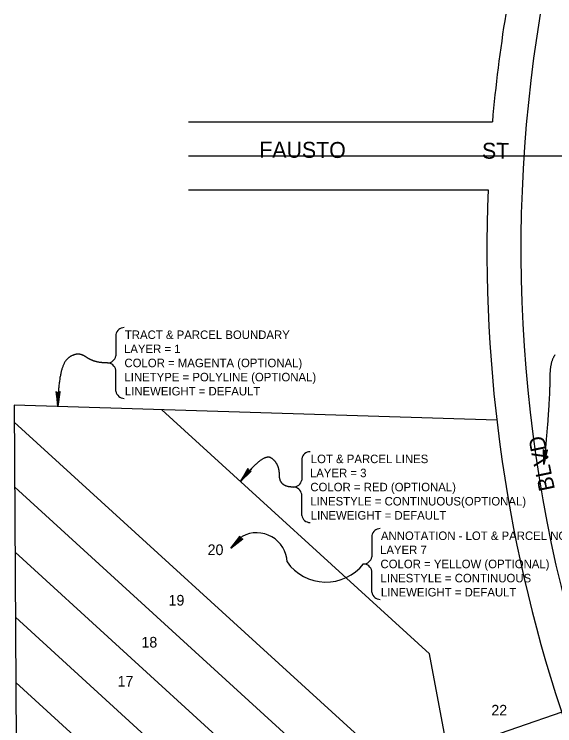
# Model space of a CAD drawing. Extents: x 6387474 to 6390971, y 1972046 to 1973920.
# Drawn here: x 6389073 to 6389581, y 1973251 to 1973920 of the extents above; entities that cross this region are included whole.
import ezdxf

# ---------------------------------------------------------------- set-up
doc = ezdxf.new("R2010")
doc.units = 0
for name, color, linetype in [('1', 7, 'Continuous'), ('2', 7, 'Continuous'), ('3', 7, 'Continuous'), ('4', 7, 'Continuous'), ('7', 7, 'Continuous'), ('8', 7, 'Continuous')]:
    doc.layers.add(name, color=color, linetype=linetype)

msp = doc.modelspace()

# ---------------------------------------------------------------- linework, layer by layer
at = {"layer": '1'}
for p, q in [((6389526.67, 1973538.46), (6389072.58, 1973552.73)), ((6389072.58, 1973552.73), (6389079.62, 1972388))]:
    msp.add_line(p, q, dxfattribs=at)
at = {"layer": '2'}
msp.add_line((6389236.57, 1973787.32), (6389892.25, 1973787.32), dxfattribs=at)
msp.add_arc((6390899.27, 1973699.34), 1350, 170.57423, 198.92361, dxfattribs=at)
at = {"layer": '3'}
for p, q in [((6389463.19, 1973318.92), (6389211.42, 1973548.37)), ((6389461.63, 1973182.31), (6389072.67, 1973536.78)), ((6389431.59, 1973148.83), (6389073.04, 1973475.59)), ((6389401.27, 1973115.57), (6389073.41, 1973414.37)), ((6389370.96, 1973082.31), (6389073.78, 1973353.15)), ((6389479.97, 1973230.27), (6389463.19, 1973318.92)), ((6389340.65, 1973049.05), (6389074.15, 1973291.92)), ((6389587.7, 1973263.79), (6389480.83, 1973227.16))]:
    msp.add_line(p, q, dxfattribs=at)
at = {"layer": '4'}
for p, q in [((6389236.57, 1973819.32), (6389522.49, 1973819.32)), ((6389236.57, 1973755.32), (6389518.4, 1973755.32))]:
    msp.add_line(p, q, dxfattribs=at)
for start, end in [(170.7944, 175.01954), (177.67854, 198.92361)]:
    msp.add_arc((6390899.27, 1973699.34), 1382, start, end, dxfattribs=at)
at = {"layer": '8'}
for p, q in [((6389168.16, 1973619.05), (6389168.16, 1973599.07)), ((6389168.16, 1973565.76), (6389168.16, 1973585.74)), ((6389111.81, 1973565.47), (6389113.61, 1973551.44)), ((6389113.61, 1973551.44), (6389115.81, 1973565.41)), ((6389570.35, 1973511.03), (6389571.01, 1973496.9)), ((6389571.01, 1973496.9), (6389574.33, 1973510.65)), ((6389343.08, 1973502.29), (6389343.08, 1973482.31)), ((6389292.5, 1973493.16), (6389285.46, 1973480.89)), ((6389285.46, 1973480.89), (6389295.65, 1973490.7)), ((6389343.08, 1973449), (6389343.08, 1973468.98)), ((6389284.72, 1973429.64), (6389276.36, 1973418.23)), ((6389276.36, 1973418.23), (6389287.2, 1973429.31)), ((6389276.36, 1973418.23), (6389287.58, 1973426.84)), ((6389409.08, 1973429.97), (6389409.08, 1973409.99)), ((6389409.08, 1973376.69), (6389409.08, 1973396.67))]:
    msp.add_line(p, q, dxfattribs=at)
for points in [[(6389124.97, 1973598.13), (6389124.64, 1973597.91), (6389124.31, 1973597.68), (6389123.98, 1973597.44), (6389123.65, 1973597.19), (6389123.32, 1973596.93), (6389122.98, 1973596.66), (6389122.65, 1973596.38), (6389122.33, 1973596.07), (6389122.01, 1973595.74), (6389121.7, 1973595.39), (6389121.39, 1973595.02), (6389121.09, 1973594.63), (6389120.8, 1973594.22), (6389120.51, 1973593.78), (6389120.22, 1973593.32), (6389119.95, 1973592.84), (6389119.68, 1973592.34), (6389119.41, 1973591.81), (6389119.15, 1973591.26), (6389118.9, 1973590.7), (6389118.65, 1973590.11), (6389118.41, 1973589.49), (6389118.17, 1973588.86), (6389117.94, 1973588.2), (6389117.72, 1973587.53), (6389117.5, 1973586.83), (6389117.29, 1973586.1), (6389117.08, 1973585.36), (6389116.88, 1973584.59), (6389116.69, 1973583.81), (6389116.5, 1973583), (6389116.32, 1973582.17), (6389116.14, 1973581.31), (6389115.97, 1973580.44), (6389115.8, 1973579.54), (6389115.64, 1973578.62), (6389115.49, 1973577.68), (6389115.34, 1973576.72), (6389115.2, 1973575.73), (6389115.07, 1973574.73), (6389114.94, 1973573.7), (6389114.81, 1973572.65), (6389114.69, 1973571.58), (6389114.58, 1973570.48), (6389114.48, 1973569.37), (6389114.38, 1973568.23), (6389114.28, 1973567.07), (6389114.19, 1973565.89), (6389114.11, 1973564.68), (6389114.03, 1973563.46), (6389113.96, 1973562.21), (6389113.9, 1973560.94), (6389113.84, 1973559.65), (6389113.79, 1973558.34), (6389113.74, 1973557), (6389113.7, 1973555.64), (6389113.66, 1973554.26), (6389113.63, 1973552.86), (6389113.61, 1973551.44)], [(6389160.27, 1973592.4), (6389159.81, 1973592.4), (6389159.34, 1973592.41), (6389158.88, 1973592.42), (6389158.42, 1973592.43), (6389157.97, 1973592.45), (6389157.52, 1973592.47), (6389157.07, 1973592.5), (6389156.62, 1973592.53), (6389156.18, 1973592.57), (6389155.74, 1973592.61), (6389155.31, 1973592.65), (6389154.87, 1973592.7), (6389154.44, 1973592.75), (6389154.02, 1973592.8), (6389153.59, 1973592.86), (6389153.17, 1973592.92), (6389152.76, 1973592.99), (6389152.34, 1973593.06), (6389151.93, 1973593.14), (6389151.52, 1973593.22), (6389151.12, 1973593.3), (6389150.72, 1973593.39), (6389150.32, 1973593.48), (6389149.92, 1973593.58), (6389149.53, 1973593.68), (6389149.14, 1973593.78), (6389148.76, 1973593.89), (6389148.38, 1973594), (6389148, 1973594.12), (6389147.62, 1973594.24), (6389147.25, 1973594.37), (6389146.88, 1973594.49), (6389146.51, 1973594.63), (6389146.15, 1973594.76), (6389145.78, 1973594.91), (6389145.43, 1973595.05), (6389145.07, 1973595.2), (6389144.72, 1973595.35), (6389144.37, 1973595.51), (6389144.03, 1973595.67), (6389143.69, 1973595.84), (6389143.35, 1973596.01), (6389143.01, 1973596.18), (6389142.68, 1973596.36), (6389142.35, 1973596.54), (6389142.02, 1973596.73), (6389141.7, 1973596.92), (6389141.38, 1973597.11), (6389141.06, 1973597.31), (6389140.75, 1973597.51), (6389140.44, 1973597.72), (6389140.13, 1973597.93), (6389139.83, 1973598.14), (6389139.53, 1973598.36), (6389139.22, 1973598.56), (6389138.92, 1973598.75), (6389138.61, 1973598.94), (6389138.31, 1973599.11), (6389138, 1973599.28), (6389137.7, 1973599.43), (6389137.39, 1973599.58), (6389137.08, 1973599.72), (6389136.77, 1973599.85), (6389136.46, 1973599.97), (6389136.15, 1973600.08), (6389135.85, 1973600.18), (6389135.53, 1973600.27), (6389135.22, 1973600.36), (6389134.91, 1973600.43), (6389134.6, 1973600.49), (6389134.29, 1973600.55), (6389133.97, 1973600.59), (6389133.66, 1973600.63), (6389133.35, 1973600.66), (6389133.03, 1973600.68), (6389132.72, 1973600.69), (6389132.4, 1973600.69), (6389132.08, 1973600.68), (6389131.77, 1973600.66), (6389131.45, 1973600.63), (6389131.13, 1973600.59), (6389130.81, 1973600.55), (6389130.49, 1973600.49), (6389130.17, 1973600.42), (6389129.85, 1973600.35), (6389129.53, 1973600.27), (6389129.21, 1973600.17), (6389128.88, 1973600.07), (6389128.56, 1973599.96), (6389128.24, 1973599.84), (6389127.91, 1973599.71), (6389127.59, 1973599.57), (6389127.26, 1973599.42), (6389126.94, 1973599.27), (6389126.61, 1973599.1), (6389126.28, 1973598.93), (6389125.96, 1973598.74), (6389125.63, 1973598.55), (6389125.3, 1973598.34), (6389124.97, 1973598.13)], [(6389581.35, 1973599.94), (6389581.08, 1973599.56), (6389580.81, 1973599.17), (6389580.56, 1973598.76), (6389580.31, 1973598.34), (6389580.07, 1973597.91), (6389579.84, 1973597.45), (6389579.61, 1973596.99), (6389579.4, 1973596.51), (6389579.19, 1973596.02), (6389578.99, 1973595.51), (6389578.8, 1973594.98), (6389578.61, 1973594.44), (6389578.43, 1973593.89), (6389578.26, 1973593.32), (6389578.1, 1973592.74), (6389577.95, 1973592.14), (6389577.8, 1973591.53), (6389577.67, 1973590.9), (6389577.54, 1973590.26), (6389577.42, 1973589.6), (6389577.3, 1973588.93), (6389577.19, 1973588.24), (6389577.1, 1973587.54), (6389577.01, 1973586.82), (6389576.92, 1973586.09), (6389576.85, 1973585.34), (6389576.78, 1973584.58), (6389576.72, 1973583.81), (6389576.67, 1973583.02)], [(6389576.67, 1973583.02), (6389576.63, 1973582.21), (6389576.59, 1973581.39), (6389576.57, 1973580.56), (6389576.55, 1973579.71), (6389576.53, 1973578.84), (6389576.53, 1973577.96), (6389576.53, 1973577.07), (6389576.52, 1973576.14), (6389576.51, 1973575.2), (6389576.5, 1973574.22), (6389576.48, 1973573.23), (6389576.46, 1973572.21), (6389576.43, 1973571.16), (6389576.4, 1973570.1), (6389576.37, 1973569), (6389576.33, 1973567.89), (6389576.29, 1973566.75), (6389576.25, 1973565.58), (6389576.2, 1973564.39), (6389576.14, 1973563.18), (6389576.09, 1973561.94), (6389576.03, 1973560.68), (6389575.96, 1973559.39), (6389575.89, 1973558.08), (6389575.82, 1973556.74), (6389575.74, 1973555.38), (6389575.66, 1973554), (6389575.58, 1973552.59), (6389575.49, 1973551.16), (6389575.4, 1973549.7), (6389575.3, 1973548.22), (6389575.2, 1973546.71), (6389575.1, 1973545.19), (6389574.99, 1973543.63), (6389574.88, 1973542.05), (6389574.76, 1973540.45), (6389574.64, 1973538.82), (6389574.52, 1973537.17), (6389574.39, 1973535.5), (6389574.26, 1973533.8), (6389574.12, 1973532.08), (6389573.98, 1973530.33), (6389573.84, 1973528.55), (6389573.69, 1973526.76), (6389573.54, 1973524.94), (6389573.38, 1973523.09), (6389573.23, 1973521.22), (6389573.06, 1973519.33), (6389572.9, 1973517.41), (6389572.72, 1973515.47), (6389572.55, 1973513.5), (6389572.37, 1973511.51), (6389572.19, 1973509.5), (6389572, 1973507.46), (6389571.81, 1973505.4), (6389571.62, 1973503.31), (6389571.42, 1973501.2), (6389571.21, 1973499.06), (6389571.01, 1973496.9)], [(6389316.06, 1973501.77), (6389315.8, 1973501.98), (6389315.53, 1973502.19), (6389315.26, 1973502.4), (6389314.98, 1973502.6), (6389314.7, 1973502.8), (6389314.41, 1973502.99), (6389314.11, 1973503.17), (6389313.81, 1973503.33), (6389313.49, 1973503.46), (6389313.17, 1973503.57), (6389312.83, 1973503.66), (6389312.49, 1973503.72), (6389312.13, 1973503.76), (6389311.77, 1973503.78), (6389311.39, 1973503.78), (6389311.01, 1973503.75), (6389310.62, 1973503.7), (6389310.22, 1973503.63), (6389309.8, 1973503.53), (6389309.38, 1973503.42), (6389308.95, 1973503.27), (6389308.51, 1973503.11), (6389308.06, 1973502.92), (6389307.6, 1973502.71), (6389307.13, 1973502.48), (6389306.65, 1973502.22), (6389306.16, 1973501.94), (6389305.67, 1973501.64), (6389305.16, 1973501.31), (6389304.64, 1973500.97), (6389304.11, 1973500.6), (6389303.58, 1973500.2), (6389303.03, 1973499.78), (6389302.48, 1973499.34), (6389301.91, 1973498.88), (6389301.33, 1973498.4), (6389300.75, 1973497.89), (6389300.16, 1973497.36), (6389299.55, 1973496.8), (6389298.94, 1973496.22), (6389298.32, 1973495.62), (6389297.68, 1973495), (6389297.04, 1973494.35), (6389296.39, 1973493.68), (6389295.73, 1973492.99), (6389295.06, 1973492.28), (6389294.38, 1973491.54), (6389293.69, 1973490.78), (6389292.99, 1973489.99), (6389292.28, 1973489.18), (6389291.56, 1973488.35), (6389290.83, 1973487.5), (6389290.09, 1973486.63), (6389289.35, 1973485.73), (6389288.59, 1973484.81), (6389287.82, 1973483.86), (6389287.04, 1973482.89), (6389286.26, 1973481.9), (6389285.46, 1973480.89)], [(6389335.19, 1973475.64), (6389334.7, 1973475.64), (6389334.23, 1973475.65), (6389333.76, 1973475.67), (6389333.3, 1973475.7), (6389332.85, 1973475.74), (6389332.41, 1973475.78), (6389331.97, 1973475.83), (6389331.55, 1973475.89), (6389331.14, 1973475.96), (6389330.73, 1973476.04), (6389330.34, 1973476.12), (6389329.95, 1973476.21), (6389329.58, 1973476.31), (6389329.21, 1973476.42), (6389328.85, 1973476.53), (6389328.51, 1973476.65), (6389328.17, 1973476.79), (6389327.84, 1973476.92), (6389327.52, 1973477.07), (6389327.21, 1973477.23), (6389326.9, 1973477.39), (6389326.61, 1973477.56), (6389326.33, 1973477.74), (6389326.05, 1973477.92), (6389325.79, 1973478.12), (6389325.53, 1973478.32), (6389325.29, 1973478.53), (6389325.05, 1973478.75), (6389324.82, 1973478.98), (6389324.6, 1973479.21), (6389324.4, 1973479.45), (6389324.2, 1973479.7), (6389324.01, 1973479.96), (6389323.82, 1973480.22), (6389323.65, 1973480.5), (6389323.49, 1973480.78), (6389323.34, 1973481.07), (6389323.19, 1973481.37), (6389323.06, 1973481.67), (6389322.93, 1973481.99), (6389322.82, 1973482.31), (6389322.71, 1973482.64), (6389322.61, 1973482.97), (6389322.52, 1973483.32), (6389322.45, 1973483.67), (6389322.38, 1973484.03), (6389322.32, 1973484.4), (6389322.26, 1973484.78), (6389322.22, 1973485.16), (6389322.19, 1973485.56), (6389322.17, 1973485.96), (6389322.15, 1973486.37), (6389322.15, 1973486.78), (6389322.15, 1973487.2), (6389322.14, 1973487.61), (6389322.12, 1973488.02), (6389322.1, 1973488.43), (6389322.08, 1973488.83), (6389322.05, 1973489.23), (6389322.01, 1973489.62), (6389321.97, 1973490.01), (6389321.93, 1973490.39), (6389321.87, 1973490.77), (6389321.82, 1973491.15), (6389321.75, 1973491.52), (6389321.68, 1973491.88), (6389321.61, 1973492.25), (6389321.53, 1973492.6), (6389321.44, 1973492.96), (6389321.35, 1973493.31), (6389321.26, 1973493.65), (6389321.15, 1973493.99), (6389321.05, 1973494.33), (6389320.93, 1973494.66), (6389320.82, 1973494.99), (6389320.69, 1973495.31), (6389320.56, 1973495.63), (6389320.43, 1973495.94), (6389320.29, 1973496.25), (6389320.14, 1973496.56), (6389319.99, 1973496.86), (6389319.83, 1973497.16), (6389319.67, 1973497.45), (6389319.5, 1973497.74), (6389319.33, 1973498.02), (6389319.15, 1973498.3), (6389318.96, 1973498.58), (6389318.77, 1973498.85), (6389318.58, 1973499.12), (6389318.38, 1973499.38), (6389318.17, 1973499.64), (6389317.96, 1973499.89), (6389317.74, 1973500.14), (6389317.52, 1973500.38), (6389317.29, 1973500.63), (6389317.06, 1973500.86), (6389316.82, 1973501.09), (6389316.57, 1973501.32), (6389316.32, 1973501.55), (6389316.06, 1973501.77)]]:
    msp.add_lwpolyline(points, dxfattribs=at)
for points in [[(6389113.61, 1973551.44), (6389112.2, 1973565.05), (6389111.81, 1973565.47)], [(6389113.61, 1973551.44), (6389112.68, 1973564.72), (6389112.2, 1973565.05)], [(6389113.61, 1973551.44), (6389113.22, 1973564.52), (6389112.68, 1973564.72)], [(6389113.8, 1973564.44), (6389113.22, 1973564.52), (6389113.61, 1973551.44)], [(6389115.81, 1973565.41), (6389115.41, 1973565), (6389113.61, 1973551.44)], [(6389115.41, 1973565), (6389114.92, 1973564.69), (6389113.61, 1973551.44)], [(6389114.92, 1973564.69), (6389114.37, 1973564.5), (6389113.61, 1973551.44)], [(6389114.37, 1973564.5), (6389113.8, 1973564.44), (6389113.61, 1973551.44)], [(6389571.01, 1973496.9), (6389570.71, 1973510.57), (6389570.35, 1973511.03)], [(6389571.01, 1973496.9), (6389571.16, 1973510.21), (6389570.71, 1973510.57)], [(6389574.34, 1973510.65), (6389573.9, 1973510.27), (6389571.01, 1973496.9)], [(6389573.9, 1973510.27), (6389573.39, 1973510), (6389571.01, 1973496.9)], [(6389571.01, 1973496.9), (6389571.68, 1973509.97), (6389571.16, 1973510.21)], [(6389573.39, 1973510), (6389572.83, 1973509.86), (6389571.01, 1973496.9)], [(6389572.25, 1973509.84), (6389571.68, 1973509.97), (6389571.01, 1973496.9)], [(6389572.83, 1973509.86), (6389572.25, 1973509.84), (6389571.01, 1973496.9)], [(6389285.46, 1973480.89), (6389292.56, 1973492.58), (6389292.5, 1973493.16)], [(6389285.46, 1973480.89), (6389292.74, 1973492.04), (6389292.56, 1973492.58)], [(6389285.46, 1973480.89), (6389293.05, 1973491.55), (6389292.74, 1973492.04)], [(6389293.46, 1973491.14), (6389293.05, 1973491.55), (6389285.46, 1973480.89)], [(6389293.96, 1973490.84), (6389293.46, 1973491.14), (6389285.46, 1973480.89)], [(6389294.51, 1973490.66), (6389293.96, 1973490.84), (6389285.46, 1973480.89)], [(6389295.66, 1973490.7), (6389295.08, 1973490.61), (6389285.46, 1973480.89)], [(6389295.08, 1973490.61), (6389294.51, 1973490.66), (6389285.46, 1973480.89)], [(6389276.36, 1973418.23), (6389284.71, 1973429.06), (6389284.72, 1973429.64)], [(6389276.36, 1973418.23), (6389284.84, 1973428.49), (6389284.71, 1973429.06)], [(6389276.36, 1973418.23), (6389285.09, 1973427.97), (6389284.84, 1973428.49)], [(6389285.45, 1973427.52), (6389285.09, 1973427.97), (6389276.36, 1973418.23)], [(6389285.91, 1973427.17), (6389285.45, 1973427.52), (6389276.36, 1973418.23)], [(6389286.43, 1973426.93), (6389285.91, 1973427.17), (6389276.36, 1973418.23)], [(6389287, 1973426.82), (6389286.43, 1973426.93), (6389276.36, 1973418.23)], [(6389287.58, 1973426.84), (6389287, 1973426.82), (6389276.36, 1973418.23)]]:
    msp.add_lwpolyline(points, close=True, dxfattribs=at)
for centre, radius, start, end in [((6389176.05, 1973617.71), 8, 90, 170.38048), ((6389160.27, 1973600.4), 8, 270, 350.38048), ((6389160.27, 1973584.4), 8, 9.61952, 90), ((6389113.83, 1973566.94), 2.5, 216.03839, 322.2986), ((6389176.05, 1973567.1), 8, 189.61952, 270), ((6389572.49, 1973512.33), 2.5, 211.39088, 317.65108), ((6389350.97, 1973500.95), 8, 90, 170.38048), ((6389295, 1973493.11), 2.5, 178.88615, 285.14635), ((6389335.19, 1973483.64), 8, 270, 350.38048), ((6389335.19, 1973467.64), 8, 9.61952, 90), ((6389350.97, 1973450.34), 8, 189.61952, 270), ((6389300.75, 1973404.14), 28.59, 2.10743, 118.29232), ((6389416.96, 1973428.64), 8, 90, 170.38048), ((6389287.2, 1973429.31), 2.5, 172.47638, 278.73658), ((6389365.95, 1973431.24), 44.95, 215.41016, 321.62389), ((6389401.19, 1973411.33), 8, 270, 350.38048), ((6389401.19, 1973395.33), 8, 9.61952, 90), ((6389416.96, 1973378.02), 8, 189.61952, 270)]:
    msp.add_arc(centre, radius, start, end, dxfattribs=at)

# ---------------------------------------------------------------- texts
at = {"layer": '2'}
for s, rotation, p in [('FAUSTO                       ST', 359.71156, (6389303.14, 1973785.61)), ('BLVD', 101.74438, (6389581.45, 1973473.59))]:
    msp.add_text(s, height=15, rotation=rotation, dxfattribs=at).set_placement(p)
at = {"layer": '7'}
for s, p in [('20', (6389254.55, 1973411.71)), ('19', (6389217.79, 1973364.22)), ('18', (6389192.27, 1973324.75)), ('17', (6389169.85, 1973288.02)), ('22', (6389521.5, 1973260.81))]:
    msp.add_text(s, height=10, dxfattribs=at).set_placement(p)
at = {"layer": '8'}
for s, p in [('TRACT & PARCEL BOUNDARY', (6389176.69, 1973614.95)), ('LAYER = 1', (6389175.88, 1973601.7)), ('COLOR = MAGENTA (OPTIONAL)', (6389176.27, 1973588.44)), ('LINETYPE = POLYLINE (OPTIONAL)', (6389176.27, 1973575.12)), ('LINEWEIGHT = DEFAULT', (6389176.66, 1973561.86)), ('LOT & PARCEL LINES', (6389351.61, 1973498.18)), ('LAYER = 3', (6389350.8, 1973484.94)), ('COLOR = RED (OPTIONAL)', (6389351.19, 1973471.68)), ('LINESTYLE = CONTINUOUS(OPTIONAL)', (6389351.19, 1973458.36)), ('LINEWEIGHT = DEFAULT', (6389351.58, 1973445.1)), ('ANNOTATION - LOT & PARCEL NO.', (6389417.61, 1973425.87)), ('LAYER 7', (6389416.8, 1973412.62)), ('COLOR = YELLOW (OPTIONAL)', (6389417.19, 1973399.36)), ('LINESTYLE = CONTINUOUS', (6389417.19, 1973386.04)), ('LINEWEIGHT = DEFAULT', (6389417.58, 1973372.79))]:
    msp.add_text(s, height=8, dxfattribs=at).set_placement(p)

doc.saveas('drawing.dxf')
